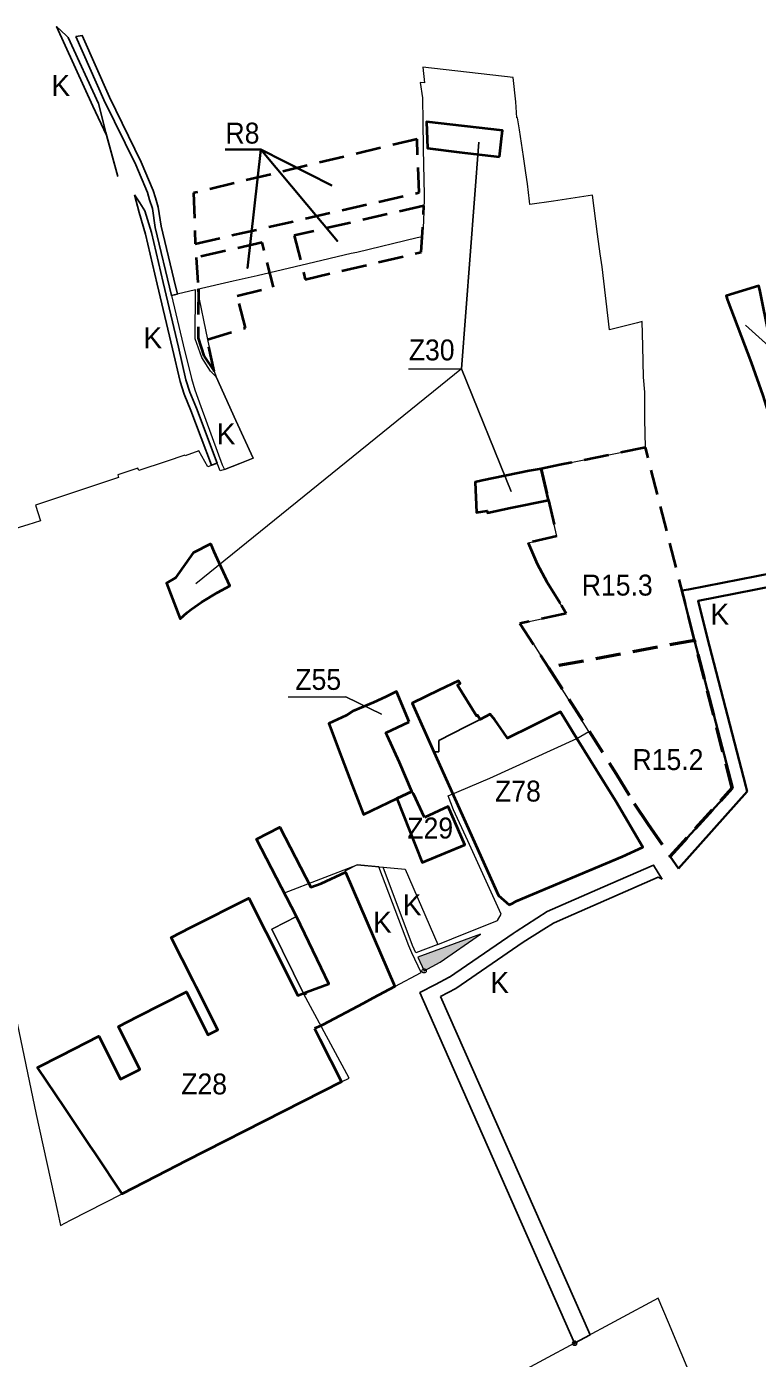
# Model space of a CAD drawing. Extents: x -650276 to -642489, y -1074425 to -1066658.
# Drawn here: x -648708 to -647869, y -1068186 to -1066658 of the extents above; entities that cross this region are included whole.
import ezdxf

# ---------------------------------------------------------------- set-up
doc = ezdxf.new("R2010")
doc.units = 0
doc.header["$LTSCALE"] = 9.6
doc.header["$PDMODE"] = 32
doc.header["$PDSIZE"] = 4.8
doc.linetypes.add('MEDIUM_DASHED', pattern=[4.5, 3, -1.5])
for name, color, linetype, lineweight in [('1', 7, 'Continuous', 13), ('4', 7, 'Continuous', 40), ('41', 7, 'Continuous', 25), ('42', 7, 'Continuous', 25), ('43', 7, 'Continuous', 13), ('45', 7, 'Continuous', 40), ('46', 7, 'Continuous', 13), ('47', 7, 'Continuous', 13), ('48', 7, 'Continuous', 35), ('61', 7, 'MEDIUM_DASHED', 40), ('62', 7, 'Continuous', 35)]:
    doc.layers.add(name, color=color, linetype=linetype, lineweight=lineweight)

msp = doc.modelspace()

# ---------------------------------------------------------------- hatches: boundary and pattern name
at = {"layer": '47'}
msp.add_hatch(color=256, dxfattribs=at).paths.add_polyline_path([(-648258.96, -1067725.37), (-648251.711, -1067741.124), (-648233.264, -1067731.288), (-648187.139, -1067699.179)])

# ---------------------------------------------------------------- linework, layer by layer
at = {"layer": '1'}
for points in [[(-648145.22, -1066762.7), (-648146.47, -1066744.59), (-648149.5, -1066716.77), (-648253.23, -1066704.92), (-648251.26, -1066722.82)], [(-648251.26, -1066722.82), (-648256.083, -1066722.388), (-648253.6, -1066739.98)], [(-648253.6, -1066739.98), (-648252.97, -1066767.53), (-648252.617, -1066797.68), (-648252.6, -1066798.46), (-648251.47, -1066851.6), (-648251.56, -1066854.93), (-648252.33, -1066881.94), (-648253.65, -1066899.2)], [(-648597.93, -1067996.72), (-648546.76, -1067970.44), (-648480.12, -1067936.55), (-648435.55, -1067913.84), (-648402.29, -1067897.02), (-648368.78, -1067879.75), (-648346.57, -1067868.56), (-648337.67, -1067864.01), (-648387.46, -1067772.25), (-648389.29, -1067768.64), (-648426.366, -1067693.402), (-648424.69, -1067692.54), (-648397.98, -1067678.79), (-648412.003, -1067651.62), (-648328.54, -1067619.51), (-648273.229, -1067624.376), (-648235.78, -1067710.79), (-648219.86, -1067704.42), (-648167.48, -1067683.45), (-648163.11, -1067676.17), (-648201.42, -1067592.09), (-648217.85, -1067556.39), (-648224, -1067540.44), (-648176.4, -1067519.99), (-648076.32, -1067474.6), (-648062.609, -1067466.599), (-648076.68, -1067444.23), (-648108.77, -1067393.23), (-648135.26, -1067351.13), (-648141.82, -1067342.88), (-648088.84, -1067331.19), (-648094.1, -1067322.05), (-648109.24, -1067298.21), (-648121.94, -1067274.29), (-648132.22, -1067250.27), (-648099.39, -1067242.54), (-648109.1, -1067201.21), (-648117.56, -1067165.19), (-647997.58, -1067141.08), (-647998.39, -1067108.26), (-647998.47, -1067077.62), (-647999.8, -1067060.36), (-648000.66, -1067024.64), (-648001.56, -1066996.48), (-648006.88, -1066997.86), (-648038.91, -1067006.14), (-648047.56, -1066933.82), (-648049.86, -1066918.87), (-648052.75, -1066896.43), (-648058.56, -1066851.51), (-648093.27, -1066856.88), (-648103.17, -1066858.32), (-648130.3, -1066862.19), (-648130.92, -1066858.62), (-648132.96, -1066838.67), (-648135.01, -1066825.88), (-648137.73, -1066807.04), (-648142.37, -1066776.69), (-648144.49, -1066762.87), (-648145.22, -1066762.7)], [(-648253.65, -1066899.2), (-648259.57, -1066900.62), (-648328.92, -1066917.33), (-648335.19, -1066918.54), (-648384.97, -1066930.38), (-648443.32, -1066943.9), (-648470.68, -1066950.24), (-648512, -1066959.81), (-648500.15, -1067017.22), (-648492.67, -1067053.5), (-648490.23, -1067060.06), (-648467.56, -1067110.02), (-648447.66, -1067153.25), (-648462.97, -1067159.24), (-648480.57, -1067166.13), (-648485.74, -1067167.74), (-648489.1, -1067158.84), (-648499.79, -1067162.97), (-648510.01, -1067144.84), (-648525.95, -1067150.5), (-648526.39, -1067149.8), (-648547.68, -1067156.93), (-648579.12, -1067167.45), (-648580.15, -1067164.76), (-648603.17, -1067172.45)], [(-648603.17, -1067172.45), (-648602.26, -1067175.2), (-648676.84, -1067200.16), (-648697.59, -1067207.11), (-648691.66, -1067224.94), (-648706.47, -1067229.51), (-648800.02, -1067258.42)], [(-648397.98, -1067678.79), (-648424.69, -1067692.54), (-648426.366, -1067693.402), (-648389.29, -1067768.64)], [(-648389.29, -1067768.64), (-648386.12, -1067767.45), (-648387.04, -1067765.67), (-648361.08, -1067755.88), (-648373.99, -1067728.95), (-648385.86, -1067704.19), (-648397.98, -1067678.79)], [(-648720.34, -1067792), (-648696.93, -1067905.76), (-648672.31, -1068017.25), (-648668.92, -1068032.96), (-648657.24, -1068027), (-648597.93, -1067996.72)]]:
    msp.add_lwpolyline(points, dxfattribs=at)
at = {"layer": '4'}
msp.add_lwpolyline([(-647876.57, -1067043.5), (-647863.04, -1067081.36), (-647853.65, -1067111.91), (-647844.3, -1067141.25), (-647847.09, -1067110.58), (-647850.07, -1067077.71), (-647852.63, -1067049.52), (-647856.11, -1067011.21), (-647866.14, -1066961.98), (-647867.46, -1066955.52), (-647905.28, -1066967.07), (-647903.5, -1066972.05)], close=True, dxfattribs=at)
at = {"layer": '4', "lineweight": 13}
msp.add_lwpolyline([(-647740.809, -1067055.795), (-647821.729, -1067055.795), (-647882.822, -1067000.815)], dxfattribs=at)
at = {"layer": '41'}
for points in [[(-648602.97, -1066830.11), (-648616.86, -1066779.79), (-648625.44, -1066746.45), (-648659.95, -1066670.89), (-648662.46, -1066668.53), (-648673.407, -1066658.275), (-648631.791, -1066749.394)], [(-648534.701, -1066965.077), (-648538.812, -1066947.891), (-648553.323, -1066887.238), (-648556.637, -1066865.397), (-648559.94, -1066854.66), (-648562.542, -1066846.219), (-648576.145, -1066813.802), (-648612.763, -1066739.165), (-648643.925, -1066668.483), (-648651.042, -1066669.551), (-648651.1, -1066669.56)], [(-648651.1, -1066669.56), (-648619.11, -1066742.12), (-648582.52, -1066816.7)], [(-648631.791, -1066749.394), (-648616.104, -1066782.727), (-648602.97, -1066830.11)], [(-648582.52, -1066816.7), (-648569.13, -1066848.61), (-648566.63, -1066856.72), (-648563.48, -1066866.96), (-648560.2, -1066888.58), (-648541.521, -1066966.657), (-648534.701, -1066965.077)], [(-648571.96, -1066869.37), (-648577.99, -1066860.17), (-648583.94, -1066851.11)], [(-648583.94, -1066851.11), (-648578.702, -1066871.259), (-648571.167, -1066896.326), (-648557.816, -1066953.444)], [(-648489.1, -1067158.84), (-648512.95, -1067095.97), (-648520.4, -1067077.42), (-648524.93, -1067063.35), (-648533.66, -1067026), (-648551, -1066951.85), (-648564.4, -1066894.52), (-648571.96, -1066869.37)], [(-648557.816, -1066953.444), (-648540.476, -1067027.594), (-648531.681, -1067065.222)], [(-648531.681, -1067065.222), (-648526.988, -1067079.8), (-648519.471, -1067098.516), (-648495.644, -1067161.326), (-648489.1, -1067158.84)], [(-647978.705, -1067635.817), (-647982.95, -1067628.73), (-647988.334, -1067619.747), (-648046.773, -1067645.314)], [(-648095.475, -1067682.994), (-647983.06, -1067633.813), (-647978.705, -1067635.817)], [(-648046.773, -1067645.314), (-648110.36, -1067673.133), (-648146.127, -1067695.8), (-648146.146, -1067695.813), (-648149.529, -1067698.132), (-648222.53, -1067748.178)], [(-648232.676, -1067770.513), (-648215.115, -1067761.28), (-648137.869, -1067708.325), (-648114.323, -1067693.403), (-648103.298, -1067686.416), (-648095.475, -1067682.994)], [(-648238.748, -1067756.759), (-648256.499, -1067766.091), (-648079.002, -1068168.139)], [(-648222.53, -1067748.178), (-648222.872, -1067748.412), (-648238.748, -1067756.759)], [(-648079.002, -1068168.139), (-648061.329, -1068158.649), (-648232.676, -1067770.513)]]:
    msp.add_lwpolyline(points, dxfattribs=at)
msp.add_point((-648079.002, -1068168.139), dxfattribs=at)
at = {"layer": '42'}
msp.add_lwpolyline([(-648153.98, -1067665.43), (-648149.933, -1067663.646), (-648146.21, -1067661.3), (-648023.96, -1067610.13), (-648000.63, -1067599.14), (-648031.77, -1067546.6), (-648045.04, -1067525.15), (-648076.32, -1067474.6), (-648081.31, -1067466.54), (-648095.28, -1067444.06), (-648133.56, -1067463.2), (-648150.46, -1067471.66), (-648155.85, -1067474.35), (-648164.24, -1067462.15), (-648166.97, -1067458.18), (-648170.38, -1067453.23), (-648175.94, -1067446.89), (-648187.44, -1067452.8), (-648203.39, -1067460.99), (-648234.68, -1067477.06), (-648234.87, -1067489.9), (-648240.51, -1067489.9), (-648166.173, -1067654.853)], close=True, dxfattribs=at)
at = {"layer": '45'}
for points in [[(-648165.33, -1066807.74), (-648162.8, -1066786.8), (-648161.58, -1066777.41), (-648248.77, -1066767.43), (-648247.78, -1066797.53), (-648211.58, -1066802.18)], [(-648165.33, -1066807.74), (-648162.8, -1066786.8), (-648161.58, -1066777.41), (-648248.77, -1066767.43), (-648247.78, -1066797.53), (-648211.58, -1066802.18)], [(-648185.185, -1067178.687), (-648193.02, -1067180.66), (-648191.44, -1067215.62), (-648179.42, -1067213.37), (-648179, -1067215.71), (-648152.5, -1067210.23), (-648109.1, -1067201.21), (-648117.51, -1067165.42), (-648131.01, -1067167.84)], [(-648496.55, -1067251.53), (-648516.47, -1067261.54), (-648536.84, -1067290.29), (-648547.17, -1067296.68), (-648531.51, -1067337.57), (-648523.55, -1067330.33), (-648518.55, -1067326.3), (-648507.25, -1067318.35), (-648488.66, -1067307.11), (-648474.69, -1067299.66), (-648486.79, -1067273.26), (-648492.62, -1067260.53)], [(-648153.98, -1067665.43), (-648149.933, -1067663.646), (-648146.21, -1067661.3), (-648023.96, -1067610.13), (-648000.63, -1067599.14), (-648031.77, -1067546.6), (-648045.04, -1067525.15), (-648076.32, -1067474.6), (-648081.31, -1067466.54), (-648095.28, -1067444.06), (-648133.56, -1067463.2), (-648150.46, -1067471.66), (-648155.85, -1067474.35), (-648164.24, -1067462.15), (-648166.97, -1067458.18), (-648170.38, -1067453.23), (-648175.94, -1067446.89), (-648187.44, -1067452.8), (-648190.23, -1067447.83), (-648191.46, -1067448.59), (-648213.34, -1067413.46), (-648210.48, -1067411.68), (-648212.32, -1067408.39), (-648234.808, -1067419.29), (-648265.197, -1067434.03), (-648240.51, -1067489.9), (-648166.173, -1067654.853)], [(-648251.33, -1067565.28), (-648263.7, -1067537.93), (-648265.757, -1067535.555), (-648282.863, -1067543.596), (-648254.04, -1067616.96), (-648204.88, -1067596.54), (-648224.16, -1067552.55)]]:
    msp.add_lwpolyline(points, close=True, dxfattribs=at)
for points in [[(-648268.67, -1067455.43), (-648283.21, -1067420.88), (-648295.66, -1067426.76), (-648309.57, -1067433.34), (-648333.48, -1067443.28), (-648341.15, -1067448.14)], [(-648341.15, -1067448.14), (-648361, -1067457.36), (-648347.51, -1067492.87)], [(-648279.86, -1067502.11), (-648294.04, -1067471.35), (-648295.409, -1067468.129), (-648268.67, -1067455.43)], [(-648347.51, -1067492.87), (-648346.27, -1067496.14), (-648334.09, -1067528.2), (-648321.36, -1067561.69), (-648282.863, -1067543.596)], [(-648282.863, -1067543.596), (-648265.757, -1067535.555), (-648279.86, -1067502.11)], [(-648433.183, -1067696.369), (-648396.605, -1067769.277), (-648387.04, -1067765.67), (-648361.08, -1067755.88), (-648369.832, -1067737.624), (-648397.98, -1067678.79), (-648443.83, -1067589.92), (-648417.12, -1067576.17), (-648381.535, -1067645.274), (-648369.949, -1067640.851), (-648342.023, -1067628.096), (-648285.254, -1067759.008), (-648310.511, -1067772.476), (-648321.623, -1067778.399), (-648367.811, -1067802.994), (-648370.113, -1067804.22), (-648377.422, -1067807.337)], [(-648377.422, -1067807.337), (-648374.84, -1067812.43), (-648371.27, -1067819.47), (-648346.57, -1067868.56), (-648413.41, -1067902.53), (-648524.72, -1067958.93), (-648546.76, -1067970.44), (-648597.93, -1067996.72), (-648629.22, -1067950.214), (-648635.249, -1067941.252), (-648664.41, -1067897.91), (-648695.27, -1067852.04), (-648668.085, -1067838.186), (-648624.76, -1067816.11), (-648600.14, -1067865.29), (-648577.78, -1067854.07), (-648602.3, -1067804.83), (-648580.14, -1067793.61), (-648524.44, -1067765.11), (-648499.7, -1067814.37), (-648488.49, -1067808.76), (-648513.23, -1067759.38), (-648516.73, -1067752.57), (-648541.86, -1067702.86), (-648519.63, -1067691.58), (-648452.72, -1067657.62), (-648433.183, -1067696.369)]]:
    msp.add_lwpolyline(points, dxfattribs=at)
at = {"layer": '45', "lineweight": 13}
msp.add_lwpolyline([(-648407.804, -1067426.736), (-648341.655, -1067426.736), (-648300.399, -1067446.681), (-648341.655, -1067426.736), (-648341.655, -1067426.736)], dxfattribs=at)
at = {"layer": '46'}
msp.add_lwpolyline([(-648269.459, -1067050.713), (-648208.812, -1067050.713), (-648188.893, -1066790.602), (-648208.812, -1067050.713), (-648151.62, -1067191.569), (-648208.812, -1067050.713), (-648513.485, -1067297.251)], dxfattribs=at)
at = {"layer": '47'}
for points in [[(-648490.23, -1067060.06), (-648496.87, -1067053.5), (-648506.78, -1067037.81), (-648514.38, -1067016.2), (-648513.842, -1066960.243), (-648541.52, -1066966.657), (-648528.01, -1067023.13)], [(-648528.01, -1067023.13), (-648518.72, -1067061.99), (-648514.86, -1067074.83), (-648507.88, -1067093.9), (-648483.31, -1067160.63), (-648480.57, -1067166.13)], [(-648480.57, -1067166.13), (-648462.97, -1067159.24), (-648447.66, -1067153.25), (-648467.56, -1067110.02), (-648490.23, -1067060.06)], [(-648101.42, -1068344.28), (-648079.33, -1068330.03), (-647929.45, -1068244.16), (-647971.35, -1068144.48), (-647982.969, -1068116.575), (-648165.28, -1068214.465), (-648108.158, -1068330.583)]]:
    msp.add_lwpolyline(points, dxfattribs=at)
for points in [[(-648303.68, -1067621.697), (-648328.54, -1067619.51), (-648342.697, -1067626.806), (-648296.891, -1067732.172), (-648285.254, -1067759.008), (-648255.016, -1067742.886), (-648265.614, -1067720.378), (-648269.27, -1067712.6)], [(-648298.632, -1067622.141), (-648273.229, -1067624.376), (-648235.78, -1067710.79), (-648261.25, -1067720.39), (-648265.08, -1067712.06)], [(-648258.96, -1067725.37), (-648251.711, -1067741.124), (-648233.264, -1067731.288), (-648187.139, -1067699.179)]]:
    msp.add_lwpolyline(points, close=True, dxfattribs=at)
msp.add_point((-648251.711, -1067741.124), dxfattribs=at)
at = {"layer": '48'}
for points in [[(-647882.66, -1067529.231), (-647926.759, -1067358.379), (-647937.355, -1067316.774), (-647828.376, -1067295.406), (-647828.104, -1067295.352), (-647831.28, -1067280.69), (-647948.488, -1067303.671)], [(-647948.488, -1067303.671), (-647955.805, -1067305.106), (-647941.289, -1067362.104)], [(-647941.289, -1067362.104), (-647897.637, -1067531.223), (-647969.29, -1067609.79), (-647959.832, -1067623.65)], [(-647959.832, -1067623.65), (-647881.085, -1067535.333), (-647882.66, -1067529.231)]]:
    msp.add_lwpolyline(points, dxfattribs=at)
at = {"layer": '61'}
for points in [[(-648259.725, -1066787.254), (-648516.098, -1066849.061), (-648514.246, -1066907.231), (-648257.498, -1066848.545)], [(-648251.815, -1066863.877), (-648400.574, -1066897.877), (-648387.967, -1066948.136), (-648254.98, -1066916.96)], [(-648437.487, -1066905.774), (-648513.271, -1066923.097), (-648510.55, -1066959.48), (-648511.02, -1067015.58), (-648504.44, -1067035.85), (-648492.67, -1067053.5), (-648500.15, -1067017.22), (-648456.62, -1067003.59), (-648466.26, -1066967), (-648424.66, -1066956.87)]]:
    msp.add_lwpolyline(points, close=True, dxfattribs=at)
for points in [[(-647941.289, -1067362.104), (-647997.58, -1067141.08), (-648095.81, -1067160.82), (-648117.51, -1067165.42), (-648109.1, -1067201.21), (-648099.39, -1067242.54)], [(-648099.39, -1067242.54), (-648132.22, -1067250.27), (-648121.94, -1067274.29), (-648110.97, -1067294.96), (-648094.1, -1067322.05), (-648088.84, -1067331.19), (-648141.82, -1067342.88), (-648108.77, -1067393.23)]]:
    msp.add_lwpolyline(points, dxfattribs=at)
at = {"layer": '61', "lineweight": 53}
for points in [[(-647941.289, -1067362.104), (-648108.77, -1067393.23), (-648031.228, -1067515.162), (-648010.57, -1067549.31)], [(-648010.57, -1067549.31), (-647994.8, -1067572.37), (-647969.29, -1067609.79), (-647898.091, -1067531.72), (-647941.289, -1067362.104)]]:
    msp.add_lwpolyline(points, dxfattribs=at)
at = {"layer": '62'}
msp.add_lwpolyline([(-648480.094, -1066799.151), (-648438.938, -1066799.151), (-648454.468, -1066935.138), (-648438.938, -1066799.151), (-648351.131, -1066904.144), (-648438.938, -1066799.151), (-648357.401, -1066840.335)], dxfattribs=at)
at = {"layer": '62', "lineweight": 13}
msp.add_lwpolyline([(-648480.094, -1066799.151), (-648438.938, -1066799.151), (-648454.468, -1066935.138), (-648438.938, -1066799.151), (-648351.131, -1066904.144), (-648438.938, -1066799.151), (-648357.401, -1066840.335)], dxfattribs=at)

# ---------------------------------------------------------------- texts
at = {"layer": '43'}
for p in [(-648679.318, -1066737.684), (-648573.703, -1067027.067), (-648489.516, -1067137.308), (-648489.516, -1067137.308), (-647923.173, -1067344.01), (-648276.169, -1067677.278), (-648310.251, -1067697.408), (-648175.732, -1067766.601)]:
    msp.add_text('K', height=24, dxfattribs=at).set_placement(p)
at = {"layer": '45', "width": 0.95}
for s, p in [('Z55', (-648399.417, -1067418.896)), ('Z29', (-648270.915, -1067589.341))]:
    msp.add_text(s, height=24, dxfattribs=at).set_placement(p)
at = {"layer": '46', "width": 0.95}
for s, p in [('Z30', (-648269.261, -1067041.062)), ('Z78', (-648170.304, -1067546.968)), ('Z28', (-648530.318, -1067882.806))]:
    msp.add_text(s, height=24, dxfattribs=at).set_placement(p)
at = {"layer": '62', "width": 0.95}
for s, p in [('R8', (-648479.548, -1066792.4)), ('R8', (-648479.548, -1066792.4)), ('R15.3', (-648070.747, -1067310.744)), ('R15.2', (-648012.511, -1067510.868))]:
    msp.add_text(s, height=24, dxfattribs=at).set_placement(p)

doc.saveas('drawing.dxf')
